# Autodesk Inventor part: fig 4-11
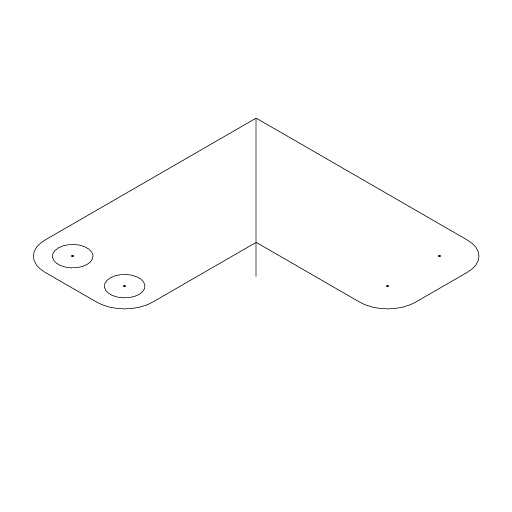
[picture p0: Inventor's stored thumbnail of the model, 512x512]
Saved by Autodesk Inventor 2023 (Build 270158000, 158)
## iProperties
Created: 2005-02
Part Number: fig 4-11
Document SubType Name: Modeling
Designer: CADCIM
Manufacturer: Standard
Standards Organization: Custom
Density: 1 g/cm^3
Material: Generic
Appearance: Default
Author: CADCIM
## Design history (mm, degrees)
sketch "Sketch1"
  geometry: L1 (5.141, 24.979)-(-32.827, 24.979); L2 (-32.827, 24.979)-(-32.827, -12.989); L3 (-27.827, -17.989)-(-18.492, -17.989); L4 (-13.492, -12.989)-(-13.492, 5.644); L5 (-13.492, 5.644)-(5.141, 5.644); L6 (10.141, 10.644)-(10.141, 19.979); L7 (-32.827, 24.979)-(-8.203, 0.354); C1 r 2.58 at (-27.827, -12.989); C2 r 2.58 at (-18.492, -12.989); A1 r 5 centre (-27.827, -12.989) between (-32.827, -12.989) and (-27.827, -17.989); A2 r 5 centre (-18.492, -12.989) between (-18.492, -17.989) and (-13.492, -12.989); A3 r 5 centre (5.141, 10.644) between (5.141, 5.644) and (10.141, 10.644); A4 r 5 centre (5.141, 19.979) between (10.141, 19.979) and (5.141, 24.979)
  constraints: 14 end point, 8 point on circle, 8 tangent, 6 centre point, 4 equal radius, 4 parallel, 3 perpendicular, 2 coincident, 1 horizontal, 1 point on line
